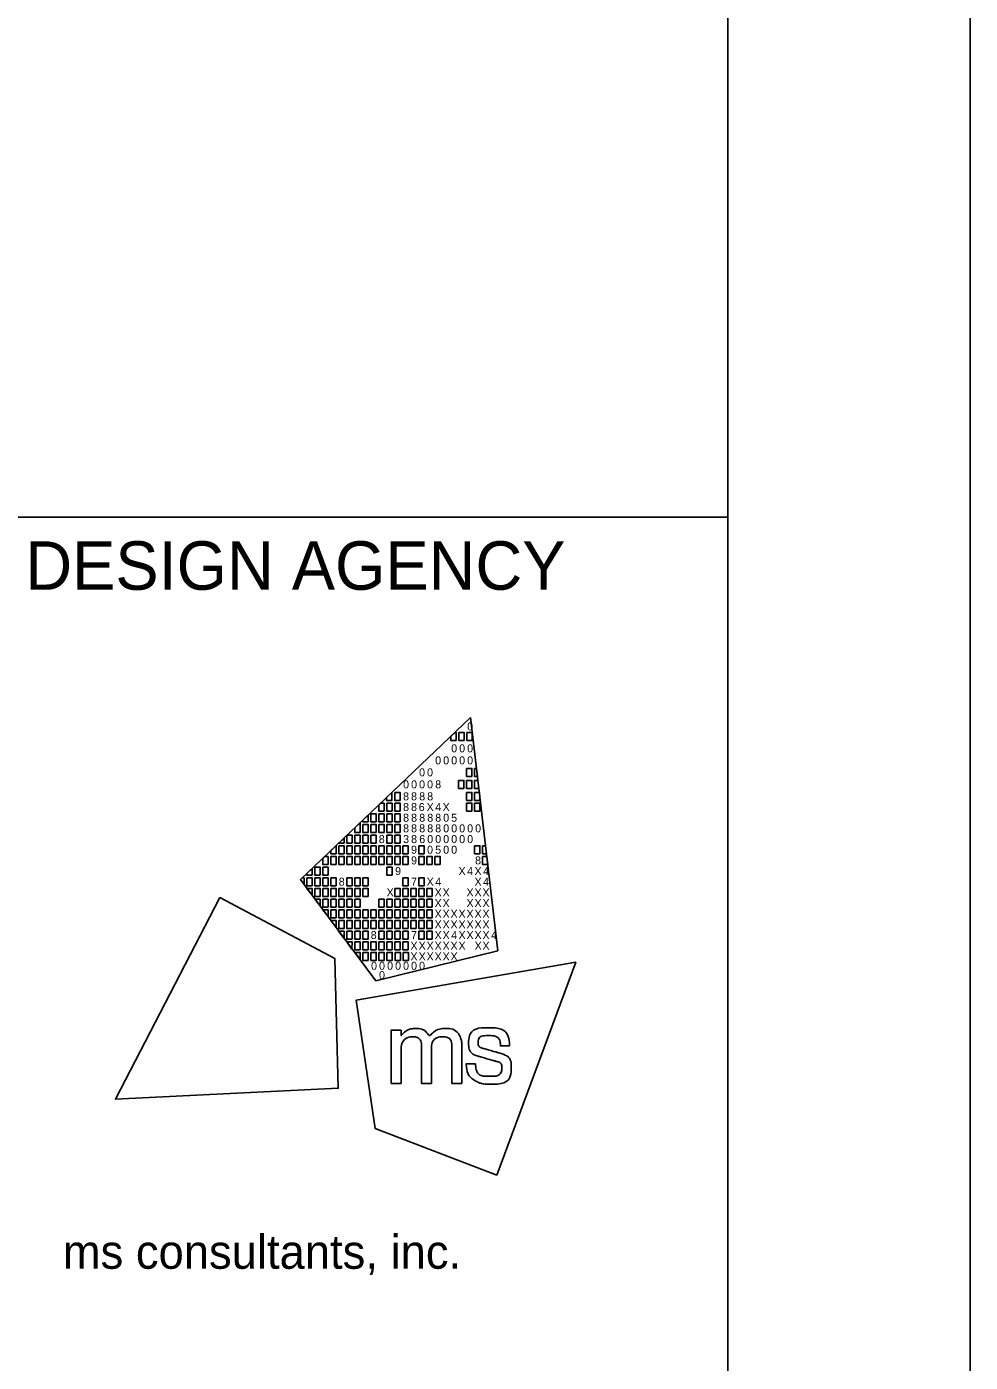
# Model space of a CAD drawing. Extents: x 0 to 74, y -27.6 to 51.8.
# Drawn here: x 32.053 to 34, y 2.756 to 5.512 of the extents above; entities that cross this region are included whole.
import ezdxf

# ---------------------------------------------------------------- set-up
doc = ezdxf.new("R2010")
doc.units = 0
for name, color, linetype in [('Default', 7, 'Continuous'), ('Level 1', 7, 'Continuous'), ('Level 2', 7, 'Continuous'), ('Level 3', 7, 'Continuous')]:
    doc.layers.add(name, color=color, linetype=linetype)

msp = doc.modelspace()

# ---------------------------------------------------------------- linework, layer by layer
at = {"layer": 'Default'}
for p, q in [((32.6175, 3.7519), (32.9688, 4.0861)), ((32.9688, 4.0861), (32.9688, 4.0861)), ((32.9688, 4.0861), (33.0253, 3.6052)), ((32.773, 3.543), (32.6175, 3.7519)), ((33.0253, 3.6052), (32.773, 3.543))]:
    msp.add_line(p, q, dxfattribs=at)
for points in [[(32.9279, 4.0472), (32.9369, 4.0558), (32.9389, 4.0558), (32.9389, 4.0393), (32.9279, 4.0393)], [(32.9444, 4.0558), (32.9554, 4.0558), (32.9554, 4.0393), (32.9444, 4.0393)], [(32.9609, 4.0558), (32.9719, 4.0558), (32.9719, 4.0393), (32.9609, 4.0393)], [(32.9606, 3.9815), (32.9716, 3.9815), (32.9716, 3.965), (32.9606, 3.965)], [(32.9771, 3.9815), (32.9811, 3.9815), (32.983, 3.965), (32.9771, 3.965)], [(32.9441, 3.9567), (32.9551, 3.9567), (32.9551, 3.9402), (32.9441, 3.9402)], [(32.9606, 3.9567), (32.9716, 3.9567), (32.9716, 3.9402), (32.9606, 3.9402)], [(32.9771, 3.9567), (32.984, 3.9567), (32.9859, 3.9402), (32.9771, 3.9402)], [(32.7953, 3.9211), (32.8064, 3.9316), (32.8064, 3.9154), (32.7953, 3.9154)], [(32.8123, 3.9319), (32.8233, 3.9319), (32.8233, 3.9154), (32.8123, 3.9154)], [(32.9606, 3.9319), (32.9716, 3.9319), (32.9716, 3.9154), (32.9606, 3.9154)], [(32.9771, 3.9319), (32.9869, 3.9319), (32.9881, 3.9218), (32.9881, 3.9154), (32.9771, 3.9154)], [(32.7627, 3.8879), (32.7737, 3.8879), (32.7737, 3.8714), (32.7627, 3.8714)], [(32.7793, 3.8879), (32.7903, 3.8879), (32.7903, 3.8714), (32.7793, 3.8714)], [(32.7958, 3.9099), (32.8068, 3.9099), (32.8068, 3.8934), (32.7958, 3.8934)], [(32.7958, 3.8879), (32.8068, 3.8879), (32.8068, 3.8714), (32.7958, 3.8714)], [(32.8123, 3.9099), (32.8233, 3.9099), (32.8233, 3.8934), (32.8123, 3.8934)], [(32.8123, 3.8879), (32.8233, 3.8879), (32.8233, 3.8714), (32.8123, 3.8714)], [(32.9606, 3.9099), (32.9716, 3.9099), (32.9716, 3.8934), (32.9606, 3.8934)], [(32.9771, 3.9099), (32.9881, 3.9099), (32.9881, 3.8934), (32.9771, 3.8934)], [(32.7462, 3.8659), (32.7572, 3.8659), (32.7572, 3.8494), (32.7462, 3.8494)], [(32.7627, 3.8659), (32.7737, 3.8659), (32.7737, 3.8494), (32.7627, 3.8494)], [(32.7793, 3.8659), (32.7903, 3.8659), (32.7903, 3.8494), (32.7793, 3.8494)], [(32.7958, 3.8659), (32.8068, 3.8659), (32.8068, 3.8494), (32.7958, 3.8494)], [(32.8123, 3.8659), (32.8233, 3.8659), (32.8233, 3.8494), (32.8123, 3.8494)], [(32.7297, 3.8439), (32.7407, 3.8439), (32.7407, 3.8273), (32.7297, 3.8273)], [(32.7462, 3.8439), (32.7572, 3.8439), (32.7572, 3.8273), (32.7462, 3.8273)], [(32.7627, 3.8439), (32.7737, 3.8439), (32.7737, 3.8273), (32.7627, 3.8273)], [(32.7958, 3.8439), (32.8068, 3.8439), (32.8068, 3.8273), (32.7958, 3.8273)], [(32.8123, 3.8439), (32.8233, 3.8439), (32.8233, 3.8273), (32.8123, 3.8273)], [(32.6967, 3.8218), (32.7077, 3.8218), (32.7077, 3.8053), (32.6967, 3.8053)], [(32.7132, 3.8218), (32.7242, 3.8218), (32.7242, 3.8053), (32.7132, 3.8053)], [(32.7297, 3.8218), (32.7407, 3.8218), (32.7407, 3.8053), (32.7297, 3.8053)], [(32.7462, 3.8218), (32.7572, 3.8218), (32.7572, 3.8053), (32.7462, 3.8053)], [(32.7627, 3.8218), (32.7737, 3.8218), (32.7737, 3.8053), (32.7627, 3.8053)], [(32.7793, 3.8218), (32.7903, 3.8218), (32.7903, 3.8053), (32.7793, 3.8053)], [(32.7958, 3.8218), (32.8068, 3.8218), (32.8068, 3.8053), (32.7958, 3.8053)], [(32.8123, 3.8218), (32.8233, 3.8218), (32.8233, 3.8053), (32.8123, 3.8053)], [(32.8288, 3.8218), (32.8398, 3.8218), (32.8398, 3.8053), (32.8288, 3.8053)], [(32.8618, 3.8218), (32.8728, 3.8218), (32.8728, 3.8053), (32.8618, 3.8053)], [(32.9771, 3.8218), (32.9881, 3.8218), (32.9881, 3.8053), (32.9771, 3.8053)], [(32.9935, 3.8218), (32.9998, 3.8218), (33.0018, 3.8053), (32.9935, 3.8053)], [(32.6471, 3.7778), (32.6581, 3.7778), (32.6581, 3.7613), (32.6471, 3.7613)], [(32.6637, 3.7778), (32.6747, 3.7778), (32.6747, 3.7613), (32.6637, 3.7613)], [(32.6802, 3.7998), (32.6912, 3.7998), (32.6912, 3.7833), (32.6802, 3.7833)], [(32.6967, 3.7998), (32.7077, 3.7998), (32.7077, 3.7833), (32.6967, 3.7833)], [(32.7132, 3.7998), (32.7242, 3.7998), (32.7242, 3.7833), (32.7132, 3.7833)], [(32.7297, 3.7998), (32.7407, 3.7998), (32.7407, 3.7833), (32.7297, 3.7833)], [(32.7462, 3.7998), (32.7572, 3.7998), (32.7572, 3.7833), (32.7462, 3.7833)], [(32.7627, 3.7998), (32.7737, 3.7998), (32.7737, 3.7833), (32.7627, 3.7833)], [(32.7793, 3.7998), (32.7903, 3.7998), (32.7903, 3.7833), (32.7793, 3.7833)], [(32.7958, 3.7998), (32.8068, 3.7998), (32.8068, 3.7833), (32.7958, 3.7833)], [(32.7958, 3.7778), (32.8068, 3.7778), (32.8068, 3.7613), (32.7958, 3.7613)], [(32.8123, 3.7998), (32.8233, 3.7998), (32.8233, 3.7833), (32.8123, 3.7833)], [(32.8288, 3.7998), (32.8398, 3.7998), (32.8398, 3.7833), (32.8288, 3.7833)], [(32.8618, 3.7998), (32.8728, 3.7998), (32.8728, 3.7833), (32.8618, 3.7833)], [(32.8783, 3.7998), (32.8893, 3.7998), (32.8893, 3.7833), (32.8783, 3.7833)], [(32.8947, 3.7998), (32.9057, 3.7998), (32.9057, 3.7833), (32.8947, 3.7833)], [(32.9935, 3.7998), (33.0024, 3.7998), (33.0044, 3.7833), (32.9935, 3.7833)], [(32.6306, 3.7558), (32.6416, 3.7558), (32.6416, 3.7393), (32.6306, 3.7393)], [(32.6471, 3.7558), (32.6581, 3.7558), (32.6581, 3.7393), (32.6471, 3.7393)], [(32.6637, 3.7558), (32.6747, 3.7558), (32.6747, 3.7393), (32.6637, 3.7393)], [(32.6802, 3.7558), (32.6912, 3.7558), (32.6912, 3.7393), (32.6802, 3.7393)], [(32.7132, 3.7558), (32.7242, 3.7558), (32.7242, 3.7393), (32.7132, 3.7393)], [(32.7297, 3.7558), (32.7407, 3.7558), (32.7407, 3.7393), (32.7297, 3.7393)], [(32.7462, 3.7558), (32.7572, 3.7558), (32.7572, 3.7393), (32.7462, 3.7393)], [(32.8288, 3.7558), (32.8398, 3.7558), (32.8398, 3.7393), (32.8288, 3.7393)], [(32.8618, 3.7558), (32.8728, 3.7558), (32.8728, 3.7393), (32.8618, 3.7393)], [(32.6306, 3.7338), (32.6416, 3.7338), (32.6416, 3.72)], [(32.6471, 3.7338), (32.6581, 3.7338), (32.6581, 3.7173), (32.6471, 3.7173)], [(32.6637, 3.7338), (32.6747, 3.7338), (32.6747, 3.7173), (32.6637, 3.7173)], [(32.6802, 3.7338), (32.6912, 3.7338), (32.6912, 3.7173), (32.6802, 3.7173)], [(32.6967, 3.7338), (32.7077, 3.7338), (32.7077, 3.7173), (32.6967, 3.7173)], [(32.7132, 3.7338), (32.7242, 3.7338), (32.7242, 3.7173), (32.7132, 3.7173)], [(32.7297, 3.7338), (32.7407, 3.7338), (32.7407, 3.7173), (32.7297, 3.7173)], [(32.7462, 3.7338), (32.7572, 3.7338), (32.7572, 3.7173), (32.7462, 3.7173)], [(32.8123, 3.7338), (32.8233, 3.7338), (32.8233, 3.7173), (32.8123, 3.7173)], [(32.8288, 3.7338), (32.8398, 3.7338), (32.8398, 3.7173), (32.8288, 3.7173)], [(32.8453, 3.7338), (32.8563, 3.7338), (32.8563, 3.7173), (32.8453, 3.7173)], [(32.8618, 3.7338), (32.8728, 3.7338), (32.8728, 3.7173), (32.8618, 3.7173)], [(32.8783, 3.7338), (32.8893, 3.7338), (32.8893, 3.7173), (32.8783, 3.7173)], [(32.6471, 3.7117), (32.6581, 3.7117), (32.6581, 3.698)], [(32.6637, 3.7117), (32.6747, 3.7117), (32.6747, 3.6952), (32.6637, 3.6952)], [(32.6802, 3.7117), (32.6912, 3.7117), (32.6912, 3.6952), (32.6802, 3.6952)], [(32.6967, 3.7117), (32.7077, 3.7117), (32.7077, 3.6952), (32.6967, 3.6952)], [(32.7132, 3.7117), (32.7242, 3.7117), (32.7242, 3.6952), (32.7132, 3.6952)], [(32.7297, 3.7117), (32.7407, 3.7117), (32.7407, 3.6952), (32.7297, 3.6952)], [(32.7793, 3.7117), (32.7903, 3.7117), (32.7903, 3.6952), (32.7793, 3.6952)], [(32.7958, 3.7117), (32.8068, 3.7117), (32.8068, 3.6952), (32.7958, 3.6952)], [(32.8123, 3.7117), (32.8233, 3.7117), (32.8233, 3.6952), (32.8123, 3.6952)], [(32.8288, 3.7117), (32.8398, 3.7117), (32.8398, 3.6952), (32.8288, 3.6952)], [(32.8453, 3.7117), (32.8563, 3.7117), (32.8563, 3.6952), (32.8453, 3.6952)], [(32.8618, 3.7117), (32.8728, 3.7117), (32.8728, 3.6952), (32.8618, 3.6952)], [(32.8783, 3.7117), (32.8893, 3.7117), (32.8893, 3.6952), (32.8783, 3.6952)], [(32.6637, 3.6897), (32.6747, 3.6897), (32.6747, 3.676)], [(32.6747, 3.6897), (32.6747, 3.6897), (32.6747, 3.6897)], [(32.6802, 3.6897), (32.6912, 3.6897), (32.6912, 3.6732), (32.6802, 3.6732)], [(32.6802, 3.6677), (32.6912, 3.6677), (32.6912, 3.654)], [(32.6967, 3.6897), (32.7077, 3.6897), (32.7077, 3.6732), (32.6967, 3.6732)], [(32.6967, 3.6677), (32.7077, 3.6677), (32.7077, 3.6512), (32.6967, 3.6512)], [(32.7132, 3.6897), (32.7242, 3.6897), (32.7242, 3.6732), (32.7132, 3.6732)], [(32.7132, 3.6677), (32.7242, 3.6677), (32.7242, 3.6512), (32.7132, 3.6512)], [(32.7297, 3.6897), (32.7407, 3.6897), (32.7407, 3.6732), (32.7297, 3.6732)], [(32.7297, 3.6677), (32.7407, 3.6677), (32.7407, 3.6512), (32.7297, 3.6512)], [(32.7462, 3.6897), (32.7572, 3.6897), (32.7572, 3.6732), (32.7462, 3.6732)], [(32.7462, 3.6677), (32.7572, 3.6677), (32.7572, 3.6512), (32.7462, 3.6512)], [(32.7627, 3.6897), (32.7737, 3.6897), (32.7737, 3.6732), (32.7627, 3.6732)], [(32.7627, 3.6677), (32.7737, 3.6677), (32.7737, 3.6512), (32.7627, 3.6512)], [(32.7793, 3.6897), (32.7903, 3.6897), (32.7903, 3.6732), (32.7793, 3.6732)], [(32.7793, 3.6677), (32.7903, 3.6677), (32.7903, 3.6512), (32.7793, 3.6512)], [(32.7958, 3.6897), (32.8068, 3.6897), (32.8068, 3.6732), (32.7958, 3.6732)], [(32.7958, 3.6677), (32.8068, 3.6677), (32.8068, 3.6512), (32.7958, 3.6512)], [(32.8123, 3.6897), (32.8233, 3.6897), (32.8233, 3.6732), (32.8123, 3.6732)], [(32.8123, 3.6677), (32.8233, 3.6677), (32.8233, 3.6512), (32.8123, 3.6512)], [(32.8288, 3.6897), (32.8398, 3.6897), (32.8398, 3.6732), (32.8288, 3.6732)], [(32.8288, 3.6677), (32.8398, 3.6677), (32.8398, 3.6512), (32.8288, 3.6512)], [(32.8453, 3.6897), (32.8563, 3.6897), (32.8563, 3.6732), (32.8453, 3.6732)], [(32.8453, 3.6677), (32.8563, 3.6677), (32.8563, 3.6512), (32.8453, 3.6512)], [(32.8618, 3.6897), (32.8728, 3.6897), (32.8728, 3.6732), (32.8618, 3.6732)], [(32.8618, 3.6677), (32.8728, 3.6677), (32.8728, 3.6512), (32.8618, 3.6512)], [(32.8783, 3.6897), (32.8893, 3.6897), (32.8893, 3.6732), (32.8783, 3.6732)], [(32.8783, 3.6677), (32.8893, 3.6677), (32.8893, 3.6512), (32.8783, 3.6512)], [(32.7077, 3.6305), (32.6965, 3.6457), (32.7077, 3.6457)], [(32.7132, 3.6457), (32.7242, 3.6457), (32.7242, 3.6292), (32.7132, 3.6292)], [(32.7297, 3.6457), (32.7407, 3.6457), (32.7407, 3.6292), (32.7297, 3.6292)], [(32.7462, 3.6457), (32.7572, 3.6457), (32.7572, 3.6292), (32.7462, 3.6292)], [(32.7793, 3.6457), (32.7903, 3.6457), (32.7903, 3.6292), (32.7793, 3.6292)], [(32.7958, 3.6457), (32.8068, 3.6457), (32.8068, 3.6292), (32.7958, 3.6292)], [(32.8123, 3.6457), (32.8233, 3.6457), (32.8233, 3.6292), (32.8123, 3.6292)], [(32.8288, 3.6457), (32.8398, 3.6457), (32.8398, 3.6292), (32.8288, 3.6292)], [(32.8618, 3.6457), (32.8728, 3.6457), (32.8728, 3.6292), (32.8618, 3.6292)], [(32.8783, 3.6457), (32.8893, 3.6457), (32.8893, 3.6292), (32.8783, 3.6292)], [(32.724, 3.6082), (32.7132, 3.6237), (32.7242, 3.6237)], [(32.7297, 3.6237), (32.7407, 3.6237), (32.7407, 3.6072), (32.7297, 3.6072)], [(32.7462, 3.6237), (32.7572, 3.6237), (32.7572, 3.6072), (32.7462, 3.6072)], [(32.7627, 3.6237), (32.7737, 3.6237), (32.7737, 3.6072), (32.7627, 3.6072)], [(32.7793, 3.6237), (32.7903, 3.6237), (32.7903, 3.6072), (32.7793, 3.6072)], [(32.7958, 3.6237), (32.8068, 3.6237), (32.8068, 3.6072), (32.7958, 3.6072)], [(32.8123, 3.6237), (32.8233, 3.6237), (32.8233, 3.6072), (32.8123, 3.6072)], [(32.8288, 3.6237), (32.8398, 3.6237), (32.8398, 3.6072), (32.8288, 3.6072)], [(32.7302, 3.6017), (32.7407, 3.6017), (32.7408, 3.5875)], [(32.7463, 3.6017), (32.7573, 3.6017), (32.7573, 3.5852), (32.7463, 3.5852)], [(32.763, 3.6017), (32.774, 3.6017), (32.774, 3.5852), (32.763, 3.5852)], [(32.7794, 3.6017), (32.7904, 3.6017), (32.7904, 3.5852), (32.7794, 3.5852)], [(32.796, 3.6017), (32.807, 3.6017), (32.807, 3.5852), (32.796, 3.5852)], [(32.8129, 3.6017), (32.8239, 3.6017), (32.8239, 3.5851), (32.8129, 3.5851)], [(32.8296, 3.6017), (32.8406, 3.6017), (32.8406, 3.5851), (32.8296, 3.5851)]]:
    msp.add_lwpolyline(points, close=True, dxfattribs=at)
for points in [[(32.7903, 3.9099), (32.7836, 3.9099), (32.7793, 3.9058), (32.7793, 3.8934), (32.7903, 3.8934), (32.7903, 3.9099)], [(32.7407, 3.8691), (32.7297, 3.8587), (32.7297, 3.8494), (32.7407, 3.8494), (32.7407, 3.8691)], [(32.7572, 3.8849), (32.7462, 3.8744), (32.7462, 3.8714), (32.7572, 3.8714), (32.7572, 3.8849)], [(32.7077, 3.8377), (32.6968, 3.8273), (32.7077, 3.8273), (32.7077, 3.8377)], [(32.7242, 3.8439), (32.7141, 3.8439), (32.7132, 3.843), (32.7132, 3.8273), (32.7242, 3.8273), (32.7242, 3.8439)], [(32.6912, 3.822), (32.6802, 3.8115), (32.6802, 3.8053), (32.6912, 3.8053), (32.6912, 3.822)], [(32.6747, 3.7998), (32.6679, 3.7998), (32.6637, 3.7958), (32.6637, 3.7833), (32.6747, 3.7833), (32.6747, 3.7998)], [(32.6251, 3.7558), (32.6216, 3.7558), (32.6175, 3.7519), (32.6251, 3.7417), (32.6251, 3.7558)], [(32.6416, 3.7749), (32.6306, 3.7644), (32.6306, 3.7613), (32.6416, 3.7613), (32.6416, 3.7749)], [(32.4512, 3.7149), (32.2359, 3.2988), (32.6956, 3.3215), (32.6884, 3.5892), (32.4512, 3.7149)], [(33.0229, 3.1422), (33.1859, 3.5814), (32.7324, 3.5029), (32.7722, 3.2381), (33.0229, 3.1422)]]:
    msp.add_lwpolyline(points, dxfattribs=at)
for points in [[(32.9595, 3.3709), (32.9595, 3.3709), (32.9595, 3.3717), (32.9595, 3.3717), (32.9595, 3.3717), (32.9603, 3.3717), (32.9603, 3.3717), (32.9603, 3.3717), (32.9783, 3.3717), (32.9783, 3.3717), (32.9783, 3.3717), (32.9789, 3.3717), (32.9789, 3.3717), (32.9789, 3.3717), (32.979, 3.371), (32.979, 3.371), (32.9803, 3.3554), (32.9887, 3.346), (33.009, 3.346), (33.0273, 3.346), (33.0333, 3.3554), (33.0333, 3.3631), (33.0333, 3.3732), (33.0256, 3.3758), (33.0175, 3.378), (33.0175, 3.378), (32.987, 3.3867), (32.987, 3.3867), (32.972, 3.3909), (32.9648, 3.4019), (32.9648, 3.4142), (32.9648, 3.4303), (32.9768, 3.4462), (33.0052, 3.4462), (33.0348, 3.4462), (33.0489, 3.4285), (33.0489, 3.4095), (33.0489, 3.4095), (33.0489, 3.4087), (33.0489, 3.4087), (33.0489, 3.4087), (33.0482, 3.4087), (33.0482, 3.4087), (33.0482, 3.4087), (33.0312, 3.4087), (33.0312, 3.4087), (33.0312, 3.4087), (33.0305, 3.4087), (33.0305, 3.4087), (33.0305, 3.4087), (33.0305, 3.4094), (33.0305, 3.4094), (33.0301, 3.4208), (33.0226, 3.43), (33.0056, 3.43), (32.9891, 3.43), (32.9843, 3.4218), (32.9843, 3.4157), (32.9843, 3.4108), (32.9869, 3.4059), (32.9959, 3.4033), (32.9959, 3.4033), (33.0255, 3.3948), (33.0255, 3.3948), (33.0462, 3.3889), (33.0527, 3.3777), (33.0527, 3.3639), (33.0527, 3.3462), (33.041, 3.3298), (33.0087, 3.3298), (32.9952, 3.3298), (32.9877, 3.3321), (32.9823, 3.3348), (32.969, 3.3414), (32.9609, 3.3536), (32.9595, 3.3709)], [(32.8048, 3.3315), (32.8048, 3.3315), (32.8048, 3.4409), (32.8048, 3.4409), (32.8048, 3.4409), (32.8255, 3.4409), (32.8255, 3.4409), (32.8255, 3.4409), (32.8255, 3.4297), (32.8255, 3.4297), (32.8346, 3.4399), (32.8457, 3.4445), (32.8555, 3.4445), (32.8688, 3.4445), (32.8791, 3.4372), (32.8837, 3.4266), (32.8915, 3.4381), (32.905, 3.4446), (32.9166, 3.4446), (32.9325, 3.4446), (32.9451, 3.435), (32.9494, 3.4213), (32.9494, 3.4212), (32.9494, 3.4212), (32.9494, 3.4212), (32.9501, 3.419), (32.9506, 3.4172), (32.9506, 3.4071), (32.9506, 3.4071), (32.9506, 3.3314), (32.9506, 3.3314), (32.9506, 3.3314), (32.9303, 3.3314), (32.9303, 3.3314), (32.9303, 3.3314), (32.9303, 3.4048), (32.9303, 3.4048), (32.9303, 3.4201), (32.9219, 3.4274), (32.911, 3.4274), (32.8995, 3.4274), (32.8879, 3.4171), (32.8879, 3.4001), (32.8879, 3.4001), (32.8879, 3.3315), (32.8879, 3.3315), (32.8879, 3.3315), (32.8674, 3.3315), (32.8674, 3.3315), (32.8674, 3.3315), (32.8674, 3.4059), (32.8674, 3.4059), (32.8674, 3.4203), (32.8588, 3.4274), (32.8496, 3.4274), (32.8384, 3.4274), (32.8254, 3.417), (32.8254, 3.3962), (32.8254, 3.3962), (32.8254, 3.3315), (32.8254, 3.3315), (32.8254, 3.3315), (32.8048, 3.3315), (32.8048, 3.3315)]]:
    msp.add_open_spline(points, degree=3, dxfattribs=at)
at = {"layer": 'Level 1'}
msp.add_lwpolyline([(0, 0), (34, 0), (34, 22), (0, 22)], close=True, dxfattribs=at)
at = {"layer": 'Level 2'}
msp.add_line((32, 4.5), (33.5, 4.5), dxfattribs=at)
msp.add_lwpolyline([(1.5, 21.5), (33.5, 21.5), (33.5, 0.5), (1.5, 0.5)], close=True, dxfattribs=at)
at = {"layer": 'Level 3'}
msp.add_line((32.75, 3.5), (32.75, 3.5), dxfattribs=at)

# ---------------------------------------------------------------- texts
at = {"layer": 'Default'}
for s, p in [('0', (32.9617, 4.0597)), ('0', (32.9288, 4.0145)), ('0', (32.9452, 4.0145)), ('0', (32.9617, 4.0145)), ('0', (32.8958, 3.9897)), ('0', (32.9123, 3.9897)), ('0', (32.9288, 3.9897)), ('0', (32.9452, 3.9897)), ('0', (32.9617, 3.9897)), ('0', (32.8625, 3.965)), ('0', (32.879, 3.965)), ('0', (32.8295, 3.9402)), ('0', (32.846, 3.9402)), ('0', (32.8625, 3.9402)), ('0', (32.879, 3.9402)), ('8', (32.8958, 3.9402)), ('8', (32.8295, 3.9154)), ('8', (32.846, 3.9154)), ('8', (32.8628, 3.9154)), ('8', (32.8793, 3.9154)), ('8', (32.8295, 3.8934)), ('8', (32.8295, 3.8713)), ('8', (32.846, 3.8934)), ('8', (32.846, 3.8713)), ('6', (32.8618, 3.8934)), ('8', (32.8628, 3.8713)), ('X', (32.8781, 3.8934)), ('8', (32.8794, 3.8713)), ('4', (32.8958, 3.8934)), ('8', (32.8958, 3.8713)), ('X', (32.911, 3.8934)), ('0', (32.9123, 3.8713)), ('5', (32.9287, 3.8713)), ('8', (32.8295, 3.8494)), ('8', (32.846, 3.8494)), ('8', (32.8628, 3.8494)), ('8', (32.8794, 3.8494)), ('8', (32.8958, 3.8494)), ('0', (32.9123, 3.8494)), ('0', (32.9288, 3.8494)), ('0', (32.9452, 3.8494)), ('0', (32.9617, 3.8494)), ('0', (32.9782, 3.8494)), ('8', (32.7793, 3.8273)), ('3', (32.8295, 3.8273)), ('8', (32.846, 3.8273)), ('6', (32.8629, 3.8273)), ('0', (32.8793, 3.8273)), ('0', (32.8958, 3.8273)), ('0', (32.9123, 3.8273)), ('0', (32.9288, 3.8273)), ('0', (32.9452, 3.8273)), ('0', (32.9617, 3.8273)), ('9', (32.846, 3.8053)), ('0', (32.879, 3.8053)), ('5', (32.8957, 3.8053)), ('0', (32.9123, 3.8053)), ('0', (32.9288, 3.8053)), ('9', (32.813, 3.7613)), ('9', (32.846, 3.7833)), ('X', (32.9439, 3.7613)), ('4', (32.9617, 3.7613)), ('X', (32.9769, 3.7613)), ('8', (32.9781, 3.7833)), ('4', (32.9946, 3.7613)), ('8', (32.6967, 3.7393)), ('7', (32.846, 3.7393)), ('X', (32.8781, 3.7393)), ('4', (32.8958, 3.7393)), ('X', (32.9769, 3.7393)), ('4', (32.9946, 3.7393)), ('X', (32.7955, 3.7173)), ('X', (32.8945, 3.7173)), ('X', (32.911, 3.7173)), ('X', (32.9604, 3.7173)), ('X', (32.9769, 3.7173)), ('X', (32.9933, 3.7173)), ('X', (32.8945, 3.6952)), ('X', (32.911, 3.6952)), ('X', (32.9604, 3.6952)), ('X', (32.9769, 3.6952)), ('X', (32.9933, 3.6952)), ('X', (32.8945, 3.6732)), ('X', (32.8945, 3.6512)), ('X', (32.911, 3.6732)), ('X', (32.911, 3.6512)), ('X', (32.9274, 3.6732)), ('X', (32.9274, 3.6512)), ('X', (32.9439, 3.6732)), ('X', (32.9439, 3.6512)), ('X', (32.9604, 3.6732)), ('X', (32.9604, 3.6512)), ('X', (32.9769, 3.6732)), ('X', (32.9769, 3.6512)), ('X', (32.9933, 3.6732)), ('X', (32.9933, 3.6512)), ('8', (32.7627, 3.6292)), ('7', (32.846, 3.6292)), ('X', (32.8945, 3.6292)), ('X', (32.911, 3.6292)), ('4', (32.9288, 3.6292)), ('X', (32.9439, 3.6292)), ('X', (32.9604, 3.6292)), ('X', (32.9769, 3.6292)), ('X', (32.9933, 3.6292)), ('4', (33.0111, 3.6292)), ('X', (32.8447, 3.6072)), ('X', (32.8616, 3.6072)), ('X', (32.878, 3.6072)), ('X', (32.8945, 3.6072)), ('X', (32.911, 3.6072)), ('X', (32.9274, 3.6072)), ('X', (32.9439, 3.6072)), ('X', (32.9771, 3.6072)), ('X', (32.9933, 3.6072)), ('X', (32.8447, 3.5851)), ('X', (32.8616, 3.5851)), ('X', (32.878, 3.5851)), ('X', (32.8945, 3.5851)), ('X', (32.911, 3.5851)), ('X', (32.9274, 3.5851)), ('0', (32.7634, 3.5659)), ('0', (32.7799, 3.5659)), ('0', (32.7799, 3.5467)), ('0', (32.7965, 3.5659)), ('0', (32.813, 3.5659)), ('0', (32.8295, 3.5659)), ('0', (32.846, 3.5659)), ('0', (32.8625, 3.5659))]:
    msp.add_text(s, height=0.0165, rotation=360, dxfattribs=at).set_placement(p)
at = {"layer": 'Level 2'}
msp.add_text('ms consultants, inc.', height=0.07, rotation=360, dxfattribs=at).set_placement((32.1273, 2.9489))
at = {"layer": 'Level 3'}
msp.add_text('DESIGN AGENCY', height=0.1, dxfattribs=at).set_placement((32.05, 4.35))

doc.saveas('drawing.dxf')
